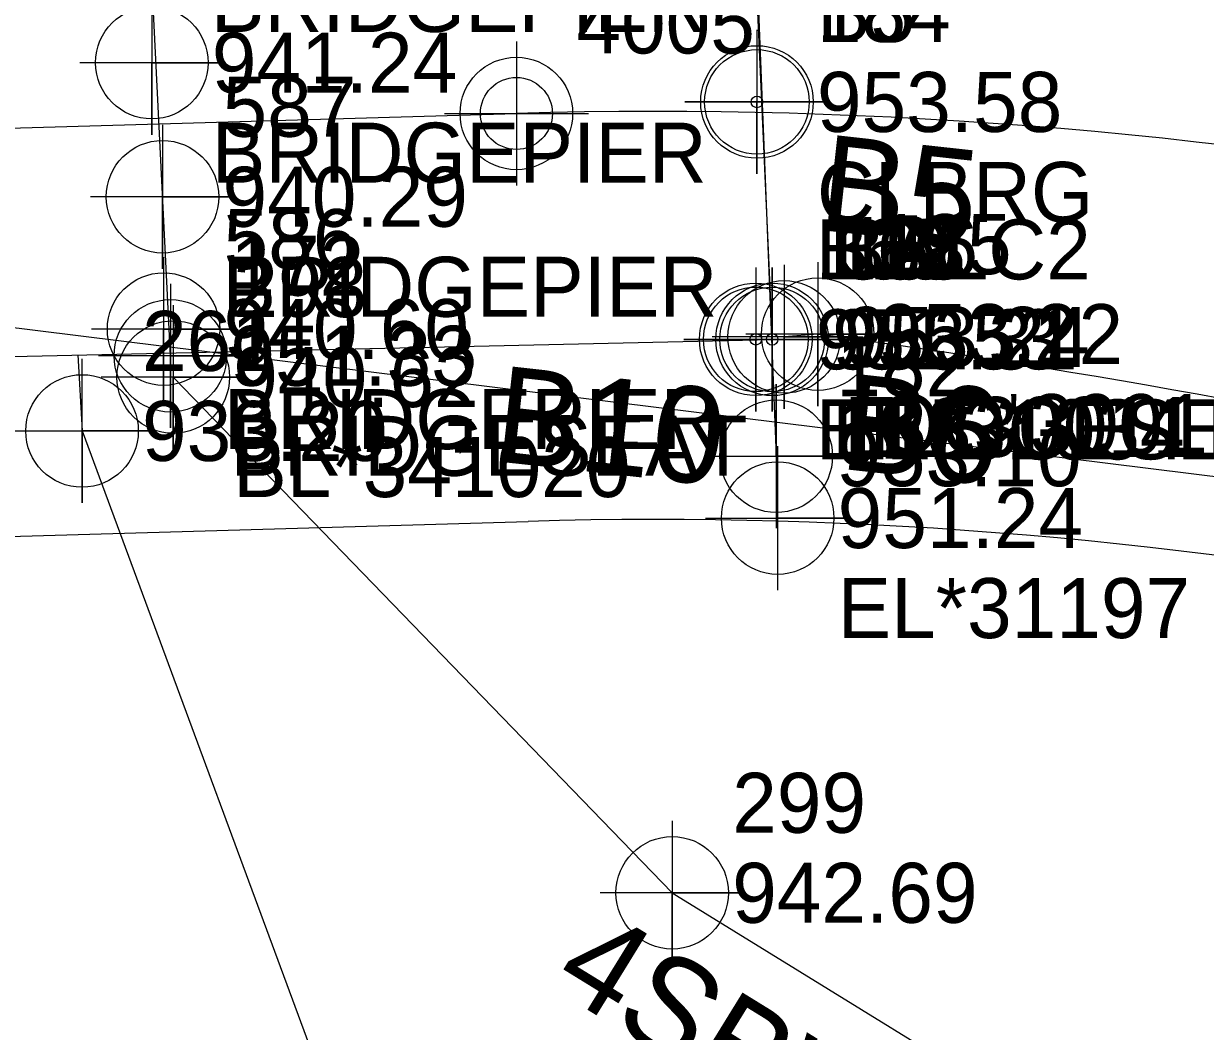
# Model space of a CAD drawing. Extents: x 1150279 to 1151282, y 655434 to 657999.
# Drawn here: x 1150767.09 to 1150816.32, y 657097.13 to 657139.11 of the extents above; entities that cross this region are included whole.
import ezdxf

# ---------------------------------------------------------------- set-up
doc = ezdxf.new("R2010")
doc.units = 0
for name, color, linetype in [('COGO Default Chain', 7, 'Continuous'), ('COGO Default Curve', 7, 'Continuous'), ('Cogo Default Point CELL', 7, 'Continuous'), ('COGO Default Point Elevation', 7, 'Continuous'), ('COGO Default Point Number', 7, 'Continuous'), ('Default Symbol CELL', 7, 'Continuous'), ('Default Symbol Cogo Comment', 7, 'Continuous'), ('Default Symbol Cogo Elevation', 7, 'Continuous'), ('Default Symbol Cogo Number', 7, 'Continuous'), ('Exist Horizontal Alignment', 7, 'Continuous'), ('Exist Horizontal Alignment Station Label', 7, 'Continuous'), ('Exist Hydro Jurisdictional Stream or Body of Water', 7, 'Continuous'), ('Exist Hydro Stream or Body of Water Cogo Elevation', 7, 'Continuous'), ('Exist Hydro Stream or Body of Water Cogo Number', 7, 'Continuous'), ('Exist Hydro Stream or Body of Water Cogo Point CELL', 7, 'Continuous'), ('Exist Other Culture Fence Line', 7, 'Continuous'), ('Exist Other Culture Fence Line Cogo Comment', 7, 'Continuous'), ('Exist Other Culture Fence Line Cogo Elevation', 7, 'Continuous'), ('Exist Other Culture Fence Line Cogo Number', 7, 'Continuous'), ('Exist Other Culture Fence Line Cogo Point CELL', 7, 'Continuous'), ('Exist Other Culture Fence Line Text', 7, 'Continuous'), ('Exist Other Culture Located Object CELL', 7, 'Continuous'), ('Exist Other Culture Located Object Text', 7, 'Continuous'), ('Exist Right of Way Line', 7, 'Continuous'), ('Exist Roads EOP', 7, 'Continuous'), ('Exist Roads EOP Cogo Comment', 7, 'Continuous'), ('Exist Roads EOP Cogo Elevation', 7, 'Continuous'), ('Exist Roads EOP Cogo Number', 7, 'Continuous'), ('Exist Roads EOP Cogo Point CELL', 7, 'Continuous'), ('Exist Structure Major Bridge Seam', 7, 'Continuous'), ('Exist Structure Major Bridge Seam Cogo Comment', 7, 'Continuous'), ('Exist Structure Major Bridge Seam Cogo Elevation', 7, 'Continuous'), ('Exist Structure Major Bridge Seam Cogo Number', 7, 'Continuous'), ('Exist Structure Major Bridge Seam Cogo Point CELL', 7, 'Continuous'), ('Exist Structure Major Bridge WW', 7, 'Continuous'), ('Exist Structure Major Bridge WW Cogo Comment', 7, 'Continuous'), ('Exist Structure Major Bridge WW Cogo Elevation', 7, 'Continuous'), ('Exist Structure Major Bridge WW Cogo Number', 7, 'Continuous'), ('Exist Structure Major Bridge WW Cogo Point CELL', 7, 'Continuous'), ('Exist Structure Major Deck Tunnel Box Culvert', 7, 'Continuous'), ('Exist Structure Major Deck Tunnel Box Culvert Cogo Elevation', 7, 'Continuous'), ('Exist Structure Major Deck Tunnel Box Culvert Cogo Number', 7, 'Continuous'), ('Exist Structure Major Deck Tunnel Box Culvert Cogo Point CELL', 7, 'Continuous')]:
    doc.layers.add(name, color=color, linetype=linetype)

msp = doc.modelspace()

# ---------------------------------------------------------------- linework, layer by layer
at = {"layer": 'COGO Default Chain'}
for p, q in [((1150614.756, 657145.261), (1150931.292, 657106.062)), ((1150755.797, 657134.446), (1150787.618, 657135.37))]:
    msp.add_line(p, q, dxfattribs=at)
msp.add_arc((1150793.42, 656935.454), 200, 65.68044, 91.66254, dxfattribs=at)
at = {"layer": 'COGO Default Curve'}
msp.add_arc((1150793.42, 656935.454), 200, 65.68044, 91.66254, dxfattribs=at)
at = {"layer": 'Cogo Default Point CELL'}
for points in [[(1150797.64, 657138.851), (1150797.64, 657135.851)], [(1150787.618, 657138.37), (1150787.618, 657135.37)], [(1150787.618, 657138.37), (1150787.618, 657135.37)], [(1150794.64, 657135.851), (1150797.64, 657135.851)], [(1150797.64, 657135.851), (1150800.64, 657135.851)], [(1150797.64, 657135.851), (1150797.64, 657132.851)], [(1150784.618, 657135.37), (1150787.618, 657135.37)], [(1150784.618, 657135.37), (1150787.618, 657135.37)], [(1150787.618, 657135.37), (1150790.618, 657135.37)], [(1150787.618, 657135.37), (1150787.618, 657132.37)], [(1150787.618, 657135.37), (1150790.618, 657135.37)], [(1150787.618, 657135.37), (1150787.618, 657132.37)], [(1150797.59, 657128.96), (1150797.59, 657125.96)], [(1150798.272, 657128.958), (1150798.272, 657125.958)], [(1150794.59, 657125.96), (1150797.59, 657125.96)], [(1150795.272, 657125.958), (1150798.272, 657125.958)], [(1150797.59, 657125.96), (1150800.59, 657125.96)], [(1150797.59, 657125.96), (1150797.59, 657122.96)], [(1150798.272, 657125.958), (1150801.272, 657125.958)], [(1150798.272, 657125.958), (1150798.272, 657122.958)]]:
    msp.add_lwpolyline(points, dxfattribs=at)
for centre in [(1150797.64, 657135.851), (1150787.618, 657135.37), (1150787.618, 657135.37), (1150797.59, 657125.96), (1150798.272, 657125.958)]:
    msp.add_circle(centre, 2.344, dxfattribs=at)
at = {"layer": 'Default Symbol CELL'}
for points in [[(1150772.428, 657140.487), (1150772.428, 657134.487), (1150772.428, 657137.487), (1150775.428, 657137.487), (1150769.428, 657137.487)], [(1150797.64, 657138.851), (1150797.64, 657132.851), (1150797.64, 657135.851), (1150800.64, 657135.851), (1150794.64, 657135.851)], [(1150772.874, 657134.9), (1150772.874, 657128.9), (1150772.874, 657131.9), (1150775.874, 657131.9), (1150769.874, 657131.9)], [(1150772.919, 657129.387), (1150772.919, 657123.387), (1150772.919, 657126.387), (1150775.919, 657126.387), (1150769.919, 657126.387)], [(1150797.59, 657128.96), (1150797.59, 657122.96), (1150797.59, 657125.96), (1150800.59, 657125.96), (1150794.59, 657125.96)], [(1150773.201, 657128.274), (1150773.201, 657122.274), (1150773.201, 657125.274), (1150776.201, 657125.274), (1150770.201, 657125.274)]]:
    msp.add_lwpolyline(points, dxfattribs=at)
for centre in [(1150772.428, 657137.487), (1150797.64, 657135.851), (1150772.874, 657131.9), (1150772.919, 657126.387), (1150797.59, 657125.96), (1150773.201, 657125.274)]:
    msp.add_circle(centre, 2.344, dxfattribs=at)
at = {"layer": 'Exist Horizontal Alignment'}
msp.add_line((1150755.797, 657134.446), (1150787.618, 657135.37), dxfattribs=at)
msp.add_arc((1150793.42, 656935.454), 200, 65.68044, 91.66254, dxfattribs=at)
at = {"layer": 'Exist Horizontal Alignment Station Label'}
msp.add_circle((1150787.618, 657135.37), 1.5, dxfattribs=at)
at = {"layer": 'Exist Hydro Jurisdictional Stream or Body of Water'}
msp.add_lwpolyline([(1150769.348, 657125.308), (1150769.521, 657122.143), (1150780.786, 657091.685), (1150798.339, 657059.295), (1150820.355, 657029.39), (1150829.476, 657003.097)], dxfattribs=at)
at = {"layer": 'Exist Hydro Stream or Body of Water Cogo Point CELL'}
msp.add_lwpolyline([(1150766.521, 657122.143), (1150772.521, 657122.143), (1150769.521, 657122.143), (1150769.521, 657119.143), (1150769.521, 657125.143)], dxfattribs=at)
msp.add_circle((1150769.521, 657122.143), 2.344, dxfattribs=at)
at = {"layer": 'Exist Other Culture Fence Line'}
msp.add_lwpolyline([(1150773.321, 657124.389), (1150794.109, 657102.9), (1150812.457, 657091.594)], dxfattribs=at)
at = {"layer": 'Exist Other Culture Fence Line Cogo Point CELL'}
for points in [[(1150773.321, 657127.389), (1150773.321, 657121.389), (1150773.321, 657124.389), (1150776.321, 657124.389), (1150770.321, 657124.389)], [(1150794.109, 657105.9), (1150794.109, 657099.9), (1150794.109, 657102.9), (1150797.109, 657102.9), (1150791.109, 657102.9)]]:
    msp.add_lwpolyline(points, dxfattribs=at)
for centre in [(1150773.321, 657124.389), (1150794.109, 657102.9)]:
    msp.add_circle(centre, 2.344, dxfattribs=at)
at = {"layer": 'Exist Other Culture Located Object CELL'}
for centre, radius in [((1150797.64, 657135.851), 2.18), ((1150797.64, 657135.851), 0.24), ((1150798.272, 657125.958), 2.18), ((1150798.272, 657125.958), 0.24)]:
    msp.add_circle(centre, radius, dxfattribs=at)
at = {"layer": 'Exist Other Culture Located Object Text'}
for radius in [2.18, 0.24]:
    msp.add_circle((1150797.59, 657125.96), radius, dxfattribs=at)
at = {"layer": 'Exist Right of Way Line'}
msp.add_line((1150756.29, 657117.453), (1150788.111, 657118.377), dxfattribs=at)
for radius in [217, 183]:
    msp.add_arc((1150793.42, 656935.454), radius, 65.68044, 91.66254, dxfattribs=at)
at = {"layer": 'Exist Roads EOP'}
msp.add_line((1150800.171, 657126.176), (1150798.776, 657126.062), dxfattribs=at)
for centre, major_axis, ratio, start_param, end_param in [((1150800.442, 656964.8), (-177.198, 34.758), 0.999524, 4.48455, 4.91412), ((1150752.571, 656773.823), (-278.809, 220.877), 0.99945, 5.05593, 5.247845)]:
    msp.add_ellipse(centre, major_axis=major_axis, ratio=ratio, start_param=start_param, end_param=end_param, dxfattribs=at)
at = {"layer": 'Exist Roads EOP Cogo Point CELL'}
for points in [[(1150798.776, 657129.062), (1150798.776, 657123.062), (1150798.776, 657126.062), (1150801.776, 657126.062), (1150795.776, 657126.062)], [(1150800.171, 657129.176), (1150800.171, 657123.176), (1150800.171, 657126.176), (1150803.171, 657126.176), (1150797.171, 657126.176)]]:
    msp.add_lwpolyline(points, dxfattribs=at)
for centre in [(1150798.776, 657126.062), (1150800.171, 657126.176)]:
    msp.add_circle(centre, 2.344, dxfattribs=at)
at = {"layer": 'Exist Structure Major Bridge Seam'}
msp.add_line((1150797.419, 657145.249), (1150798.272, 657125.958), dxfattribs=at)
at = {"layer": 'Exist Structure Major Bridge Seam Cogo Point CELL'}
msp.add_lwpolyline([(1150798.272, 657128.958), (1150798.272, 657122.958), (1150798.272, 657125.958), (1150801.272, 657125.958), (1150795.272, 657125.958)], dxfattribs=at)
msp.add_circle((1150798.272, 657125.958), 2.344, dxfattribs=at)
at = {"layer": 'Exist Structure Major Bridge WW'}
msp.add_lwpolyline([(1150797.283, 657150.154), (1150798.443, 657121.09), (1150798.503, 657118.513)], dxfattribs=at)
at = {"layer": 'Exist Structure Major Bridge WW Cogo Point CELL'}
for points in [[(1150795.443, 657121.09), (1150801.443, 657121.09), (1150798.443, 657121.09), (1150798.443, 657124.09), (1150798.443, 657118.09)], [(1150795.503, 657118.513), (1150801.503, 657118.513), (1150798.503, 657118.513), (1150798.503, 657121.513), (1150798.503, 657115.513)]]:
    msp.add_lwpolyline(points, dxfattribs=at)
for centre in [(1150798.443, 657121.09), (1150798.503, 657118.513)]:
    msp.add_circle(centre, 2.344, dxfattribs=at)
at = {"layer": 'Exist Structure Major Deck Tunnel Box Culvert'}
msp.add_line((1150717.448, 657124.141), (1150798.272, 657125.958), dxfattribs=at)
msp.add_lwpolyline([(1150773.201, 657125.274), (1150772.231, 657144.932)], dxfattribs=at)
at = {"layer": 'Exist Structure Major Deck Tunnel Box Culvert Cogo Point CELL'}
msp.add_lwpolyline([(1150795.272, 657125.958), (1150801.272, 657125.958), (1150798.272, 657125.958), (1150798.272, 657128.958), (1150798.272, 657122.958)], dxfattribs=at)
msp.add_circle((1150798.272, 657125.958), 2.344, dxfattribs=at)

# ---------------------------------------------------------------- texts
at = {"layer": 'COGO Default Point Elevation'}
for s, p in [('953.58', (1150800.14, 657134.601)), ('951.53', (1150800.09, 657124.71)), ('953.31', (1150800.772, 657124.708))]:
    msp.add_text(s, height=2.5, dxfattribs=at).set_placement(p)
at = {"layer": 'COGO Default Point Number'}
for s, p in [('B5', (1150800.14, 657138.351)), ('4005', (1150790.118, 657137.87)), ('B10', (1150800.09, 657128.46)), ('B6', (1150800.772, 657128.458))]:
    msp.add_text(s, height=2.5, dxfattribs=at).set_placement(p)
at = {"layer": 'Default Symbol Cogo Comment'}
for s, p in [('BRIDGEPIER', (1150774.89, 657138.767)), ('BRIDGEPIER', (1150774.928, 657132.487)), ('CLBRG', (1150800.14, 657130.851)), ('BRIDGEPIER', (1150775.374, 657126.9)), ('BRIDGEPIER', (1150775.419, 657121.387)), ('BRIDGESEAT', (1150800.09, 657120.96)), ('BRIDGESEAT', (1150775.701, 657120.274))]:
    msp.add_text(s, height=2.5, dxfattribs=at).set_placement(p)
at = {"layer": 'Default Symbol Cogo Elevation'}
for s, p in [('941.24', (1150774.928, 657136.237)), ('953.58', (1150800.14, 657134.601)), ('940.29', (1150775.374, 657130.65)), ('940.60', (1150775.419, 657125.137)), ('951.53', (1150800.09, 657124.71)), ('951.33', (1150775.701, 657124.024))]:
    msp.add_text(s, height=2.5, dxfattribs=at).set_placement(p)
at = {"layer": 'Default Symbol Cogo Number'}
for s, p in [('184', (1150800.14, 657138.351)), ('587', (1150775.374, 657134.4)), ('586', (1150775.419, 657128.887)), ('169', (1150800.09, 657128.46)), ('172', (1150775.701, 657127.774))]:
    msp.add_text(s, height=2.5, dxfattribs=at).set_placement(p)
at = {"layer": 'Exist Hydro Stream or Body of Water Cogo Elevation'}
msp.add_text('933.20', height=2.5, dxfattribs=at).set_placement((1150772.021, 657120.893))
at = {"layer": 'Exist Hydro Stream or Body of Water Cogo Number'}
msp.add_text('261', height=2.5, dxfattribs=at).set_placement((1150772.021, 657124.643))
at = {"layer": 'Exist Other Culture Fence Line Cogo Comment'}
msp.add_text('BL*341020', height=2.5, dxfattribs=at).set_placement((1150775.821, 657119.389))
at = {"layer": 'Exist Other Culture Fence Line Cogo Elevation'}
for s, p in [('940.62', (1150775.821, 657123.139)), ('942.69', (1150796.609, 657101.65))]:
    msp.add_text(s, height=2.5, dxfattribs=at).set_placement(p)
at = {"layer": 'Exist Other Culture Fence Line Cogo Number'}
for s, p in [('298', (1150775.821, 657126.889)), ('299', (1150796.609, 657105.4))]:
    msp.add_text(s, height=2.5, dxfattribs=at).set_placement(p)
at = {"layer": 'Exist Other Culture Fence Line Text'}
msp.add_text('4SBW', height=4, rotation=328.358, dxfattribs=at).set_placement((1150788.996, 657099.003))
at = {"layer": 'Exist Other Culture Located Object Text'}
for s, p in [('B5', (1150800.118, 657130.531)), ('B10', (1150786.588, 657120.897)), ('B6', (1150801.028, 657120.579))]:
    msp.add_text(s, height=4, rotation=353.6867, dxfattribs=at).set_placement(p)
at = {"layer": 'Exist Roads EOP Cogo Comment'}
for s, p in [('EL*30011', (1150801.276, 657121.062)), ('OC*30011', (1150802.671, 657121.176))]:
    msp.add_text(s, height=2.5, dxfattribs=at).set_placement(p)
at = {"layer": 'Exist Roads EOP Cogo Elevation'}
for s, p in [('953.24', (1150801.276, 657124.812)), ('953.22', (1150802.671, 657124.926))]:
    msp.add_text(s, height=2.5, dxfattribs=at).set_placement(p)
at = {"layer": 'Exist Roads EOP Cogo Number'}
for s, p in [('126', (1150801.276, 657128.562)), ('125', (1150802.671, 657128.676))]:
    msp.add_text(s, height=2.5, dxfattribs=at).set_placement(p)
at = {"layer": 'Exist Structure Major Bridge Seam Cogo Comment'}
msp.add_text('EL*31034 EL*31015', height=2.5, dxfattribs=at).set_placement((1150800.772, 657120.958))
at = {"layer": 'Exist Structure Major Bridge Seam Cogo Elevation'}
msp.add_text('953.31', height=2.5, dxfattribs=at).set_placement((1150800.772, 657124.708))
at = {"layer": 'Exist Structure Major Bridge Seam Cogo Number'}
msp.add_text('168', height=2.5, dxfattribs=at).set_placement((1150800.772, 657128.458))
at = {"layer": 'Exist Structure Major Bridge WW Cogo Comment'}
msp.add_text('EL*31197', height=2.5, dxfattribs=at).set_placement((1150801.003, 657113.513))
at = {"layer": 'Exist Structure Major Bridge WW Cogo Elevation'}
for s, p in [('953.10', (1150800.943, 657119.84)), ('951.24', (1150801.003, 657117.263))]:
    msp.add_text(s, height=2.5, dxfattribs=at).set_placement(p)
at = {"layer": 'Exist Structure Major Bridge WW Cogo Number'}
for s, p in [('182', (1150800.943, 657123.59)), ('183', (1150801.003, 657121.013))]:
    msp.add_text(s, height=2.5, dxfattribs=at).set_placement(p)
at = {"layer": 'Exist Structure Major Deck Tunnel Box Culvert Cogo Elevation'}
msp.add_text('953.31', height=2.5, dxfattribs=at).set_placement((1150800.772, 657124.708))
at = {"layer": 'Exist Structure Major Deck Tunnel Box Culvert Cogo Number'}
msp.add_text('CALC2', height=2.5, dxfattribs=at).set_placement((1150800.772, 657128.458))

doc.saveas('drawing.dxf')
